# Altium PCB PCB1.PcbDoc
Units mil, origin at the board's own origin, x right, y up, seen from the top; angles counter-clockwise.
Board outline 6000 x 4000 mil, 2 copper layers (Top Layer, Bottom Layer); 53 components, 98 nets, 821 pads, 0 vias.
Unrouted connection lines stored in the file: 466.
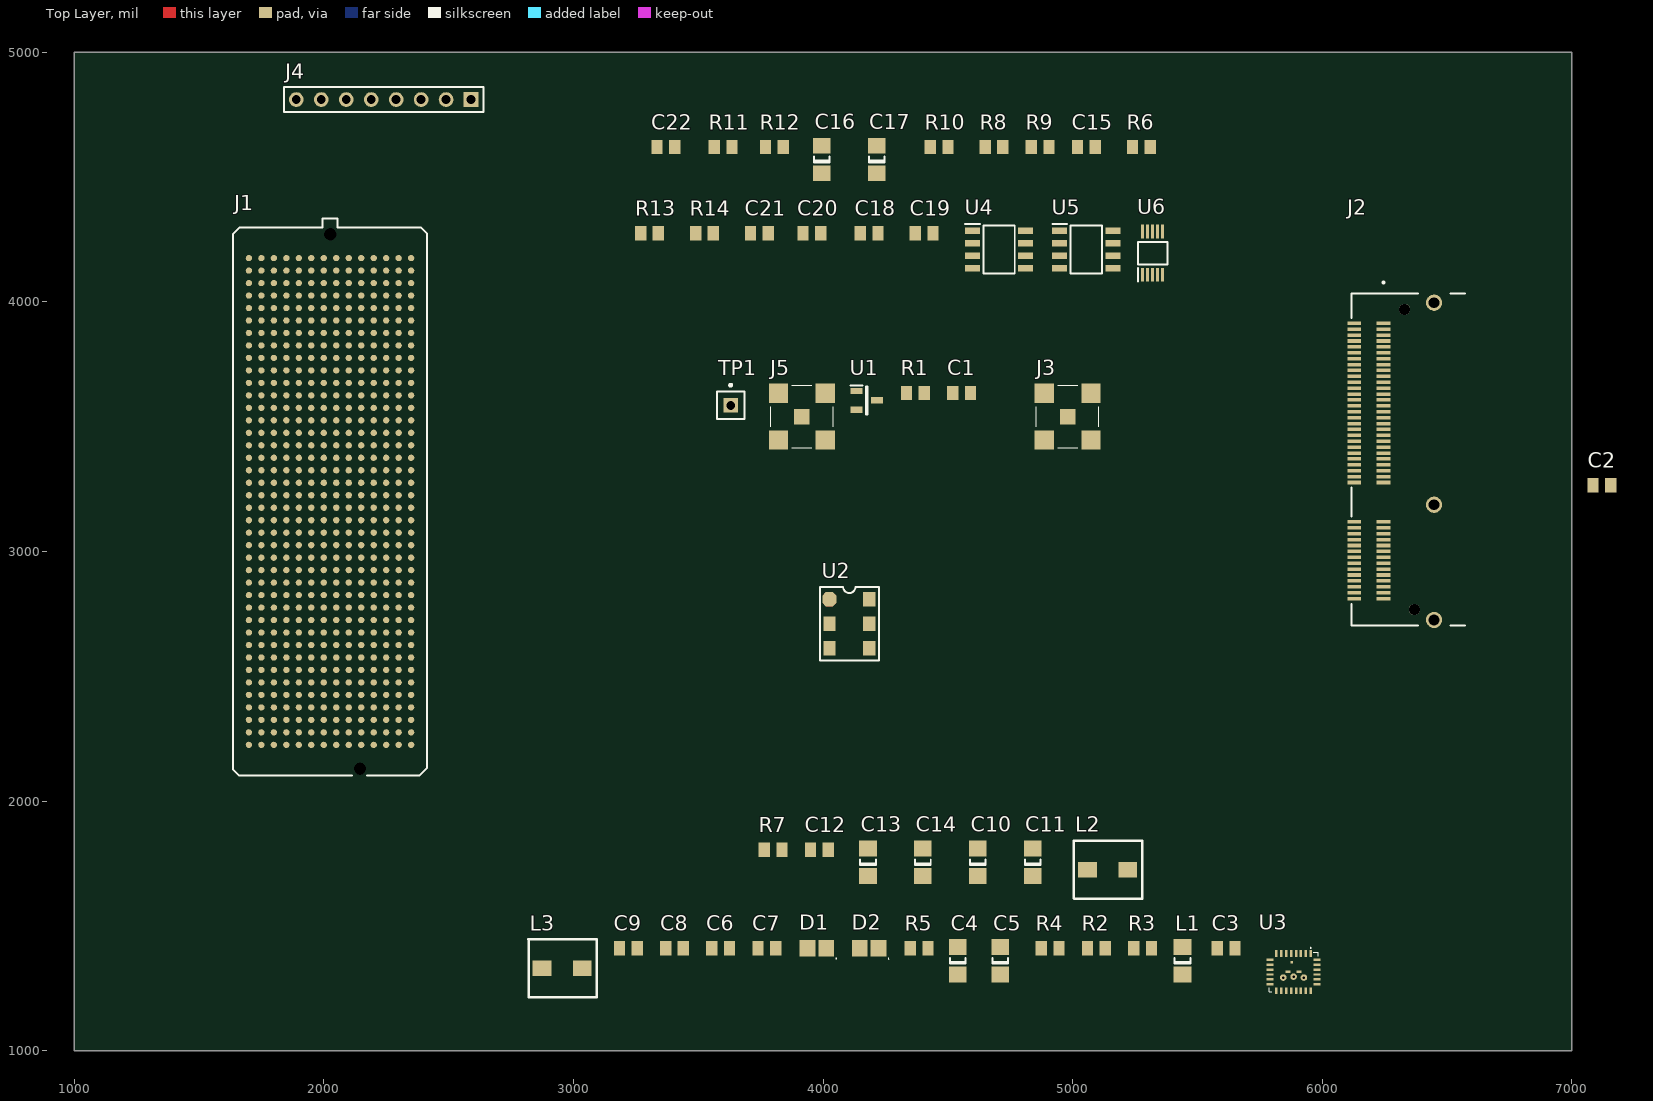
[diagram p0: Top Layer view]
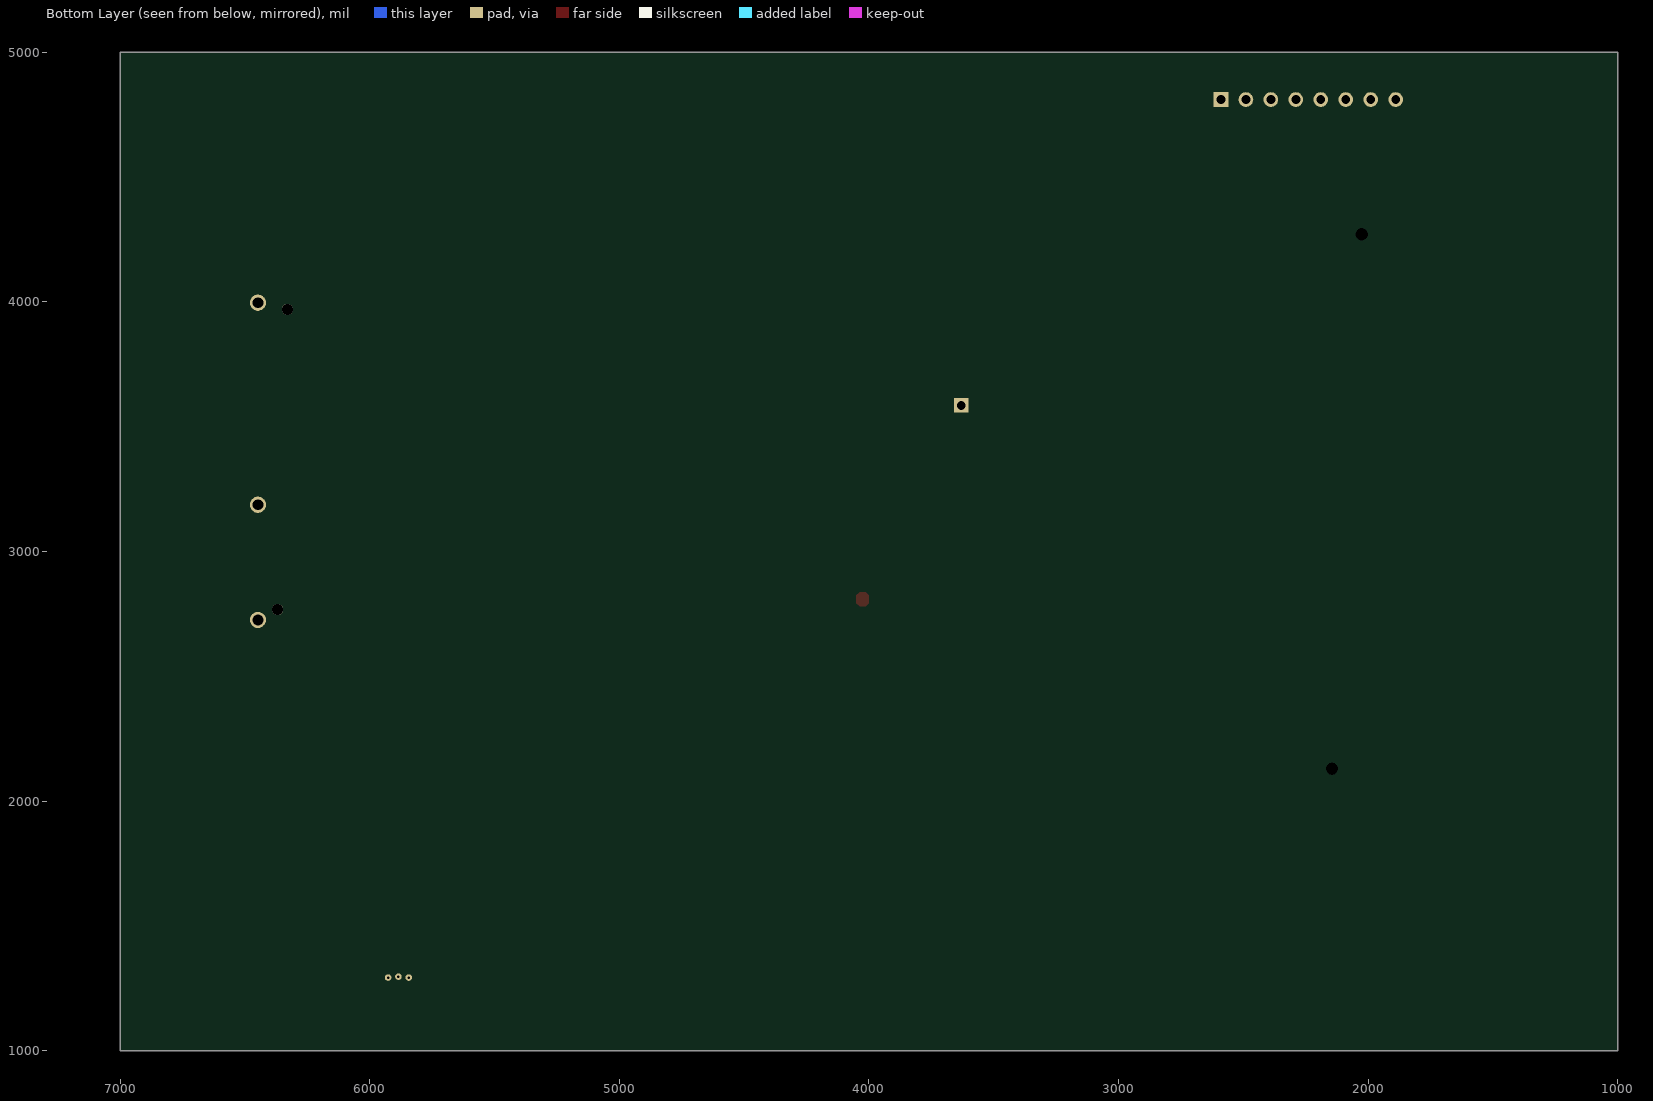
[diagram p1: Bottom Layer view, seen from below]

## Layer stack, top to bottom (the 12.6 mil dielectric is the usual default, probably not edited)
Top Solder: solder mask 0.4, Solder Resist, Dk 3.5
Top Layer: signal copper 1.4
Dielectric 1: dielectric 12.6, FR-4, Dk 4.8
Bottom Layer: signal copper 1.4
Bottom Solder: solder mask 0.4, Solder Resist, Dk 3.5

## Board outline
1000,1000 7000,1000 7000,5000 1000,5000

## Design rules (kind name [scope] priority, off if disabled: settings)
Clearance [All] p1: gap=10 ignorepadtopadclearanceinfootprint=FALSE
DiffPairsRouting [All] p1: maxlimit=10 minlimit=10 mostfreqgap=10 toplayer_minwidth=15 toplayer_maxwidth=15 toplayer_prefwidth=15 bottomlayer_minwidth=15 bottomlayer_maxwidth=15 bottomlayer_prefwidth=15 maxuncoupledlength=500
PolygonConnect [All] p1: connectstyle=Relief reliefconductorwidth=10 reliefentries=4 polygonreliefangle="90 Angle" airgapwidth=10
RoutingVias [All] p1: holewidth=28 width=50 viastyle="Through Hole" minholewidth=28 minwidth=50 maxholewidth=28 maxwidth=50
SolderMaskExpansion [All] p1: expansion=4 istentingtop=FALSE
SupplyNets "Schematic Supply Nets_4" [InNet('3V3')] p1: voltage=0.000
SupplyNets "Schematic Supply Nets_3" [InNet('2V5')] p2: voltage=0.000
SupplyNets "Schematic Supply Nets_2" [InNet('GND')] p3: voltage=0.000
SupplyNets "Schematic Supply Nets_1" [InNet('1V5')] p4: voltage=0.000
SupplyNets "Schematic Supply Nets" [InNet('VADJ_FMC')] p5: voltage=0.000
Width [All] p1: maxlimit=10 minlimit=10 preferedwidth=10
29 further rules are at their usual default settings.

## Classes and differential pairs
component class TP4_Compact_FMC_Sht2: C3 C4 C5 C6 C7 C8 C9 C10 C11 C12 C13 C14 C15 C16 C17 C18 C19 C20 C21 C22 D1 D2 J2 L1 L2 L3 R2 R3 R4 R5 R6 R7 R8 R9 R10 R11 R12 R13 R14 U3 U4 U5 U6
component class TP4_Compact_FMC_Sht1: C1 C2 J1 J3 J4 J5 R1 TP1 U1 U2
differential pair TPX4_RefClk: +TPX4_RefClk_P -TPX4_RefClk_N
differential pair TO_SYNC_B: +TO_SYNC_B_P -TO_SYNC_B_N
differential pair TESTOUT_T: +TESTOUT_T_P -TESTOUT_T_N
differential pair TESTOUT_B: +TESTOUT_B_P -TESTOUT_B_N
differential pair SHUTTER_B: +SHUTTER_B_P -SHUTTER_B_N
differential pair SERIAL_OUT5_T: +SERIAL_OUT5_T_P -SERIAL_OUT5_T_N
differential pair SERIAL_OUT5_B: +SERIAL_OUT5_B_P -SERIAL_OUT5_B_N
differential pair SERIAL_OUT4_T: +SERIAL_OUT4_T_P -SERIAL_OUT4_T_N
differential pair SERIAL_OUT4_B: +SERIAL_OUT4_B_P -SERIAL_OUT4_B_N
differential pair SERIAL_OUT3_T: +SERIAL_OUT3_T_P -SERIAL_OUT3_T_N
differential pair SERIAL_OUT3_B: +SERIAL_OUT3_B_P -SERIAL_OUT3_B_N
differential pair SERIAL_OUT2_T: +SERIAL_OUT2_T_P -SERIAL_OUT2_T_N
differential pair SERIAL_OUT2_B: +SERIAL_OUT2_B_P -SERIAL_OUT2_B_N
differential pair SERIAL_OUT1_T: +SERIAL_OUT1_T_P -SERIAL_OUT1_T_N
differential pair SERIAL_OUT1_B: +SERIAL_OUT1_B_P -SERIAL_OUT1_B_N
differential pair SERIAL_OUT0_T: +SERIAL_OUT0_T_P -SERIAL_OUT0_T_N
differential pair SERIAL_OUT0_B: +SERIAL_OUT0_B_P -SERIAL_OUT0_B_N
differential pair SC_DATA_OUT_B: +SC_DATA_OUT_B_P -SC_DATA_OUT_B_N
differential pair SC_DATA_IN_B: +SC_DATA_IN_B_P -SC_DATA_IN_B_N
differential pair SC_CLOCK_OUT_B: +SC_CLOCK_OUT_B_P -SC_CLOCK_OUT_B_N
differential pair SC_CLOCK_IN_B: +SC_CLOCK_IN_B_P -SC_CLOCK_IN_B_N
differential pair RESET_B: +RESET_B_P -RESET_B_N
differential pair MGTREF: +MGTREF_P -MGTREF_N

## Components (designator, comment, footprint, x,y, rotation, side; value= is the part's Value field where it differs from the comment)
C1 "Cap" CAP0805 4555,3635 r0 top value="10uF 16v 0805"
C2 "Cap" CAP0805 7120,3265 r0 top value="10uF 16v 0805"
C3 "Cap" CAP0805 5615,1410 r0 top value="10uF 16v 0805"
C4 "Cap" 1206 4540,1360 r90 top value="47uF 25v 1206"
C5 "Cap" 1206 4710,1360 r90 top value="47uF 25v 1206"
C6 "Cap" CAP0805 3590,1410 r0 top value=DNP
C7 "Cap" CAP0805 3775,1410 r0 top value=DNP
C8 "Cap" CAP0805 3405,1410 r0 top value="0.1uF 16v 0805"
C9 "Cap" CAP0805 3220,1410 r0 top value="0.1uF 16v 0805"
C10 "Cap" 1206 4620,1755 r90 top value="47uF 25v 1206"
C11 "Cap" 1206 4840,1755 r90 top value="47uF 25v 1206"
C12 "Cap" CAP0805 3985,1805 r0 top value="22pF 0805"
C13 "Cap" 1206 4180,1755 r90 top value="47uF 25v 1206"
C14 "Cap" 1206 4400,1755 r90 top value="47uF 25v 1206"
C15 "Cap" CAP0805 5055,4620 r0 top value="22pF 0805"
C16 "Cap" 1206 3995,4570 r90 top value="47uF 25v 1206"
C17 "Cap" 1206 4215,4570 r90 top value="47uF 25v 1206"
C18 "Cap" CAP0805 4185,4275 r0 top value="0.1uF 16v 0805"
C19 "Cap" CAP0805 4405,4275 r0 top value="0.1uF 16v 0805"
C20 "Cap" CAP0805 3955,4275 r0 top value="0.1uF 16v 0805"
C21 "Cap" CAP0805 3745,4275 r0 top value="0.1uF 16v 0805"
C22 "Cap" CAP0805 3370,4620 r0 top value="0.1uF 16v 0805"
D1 "LED_GRN 0603" LED0603 3975,1410 r0 top
D2 "LED_GRN 0603" LED0603 4185,1410 r0 top
J1 "ASP_184330_01" SAMTEC_ASP_184330_01 2025,3200 r90 top
J2 "HSEC6-042-01-S-RA-WT-X" SAMTEC_HSEC6-042-01-S-RA-WT-X 6329.65,3368.33 r90 top
J3 "SMA_V" SMA_Vert 4980,3540 r0 top
J4 "Header 8" HDR1X8 2590,4810 r180 top
J5 "SMA_V" SMA_Vert 3915,3540 r0 top
L1 "Inductor Iron" 1206 5440,1360 r90 top value="bead 1206"
L2 "Inductor Iron" Inductor_5.6mm 5140,1725 r0 top value=10mH
L3 "Inductor Iron" Inductor_5.6mm 2955,1330 r0 top value=10mH
R1 "Res" CAP0805 4370,3635 r0 top value=zero
R2 "Res1" CAP0805 5095,1410 r0 top value=15k
R3 "Res1" CAP0805 5280,1410 r0 top value=15k
R4 "Res1" CAP0805 4910,1410 r0 top value=150k
R5 "Res1" CAP0805 4385,1410 r0 top value=zero
R6 "Res1" CAP0805 5275,4620 r0 top value=45.3k
R7 "Res1" CAP0805 3800,1805 r0 top value=15k
R8 "Res1" CAP0805 4685,4620 r0 top value=10k
R9 "Res1" CAP0805 4870,4620 r0 top value=10k
R10 "Res1" CAP0805 4465,4620 r0 top value=zero
R11 "Res" CAP0805 3600,4620 r0 top value=".02 1W 1206"
R12 "Res" CAP0805 3805,4620 r0 top value=".02 1W 1206"
R13 "Res1" CAP0805 3305,4275 r0 top value=zero
R14 "Res1" CAP0805 3525,4275 r0 top value=zero
TP1 "through-hole pad" Pin1 3630,3585 r0 top
U1 "MCP1700T-2502E_TT" SOT95P237X112-3N 4175,3605 r0 top
U2 "SIT9365AI-2E2-25E160.00" osc_7mm_5mm 4025.55,2808.43 r0 top
U3 "LTC3636EUFD#PBF" LTC3636EUFDPBF 5885,1315 r0 top
U4 "AD8202WYRZ" SOIC127P600X175-8N 4705,4210 r0 top
U5 "AD8202WYRZ" SOIC127P600X175-8N 5055,4210 r0 top
U6 "ADS1015LIDGSR" SOP50P490X110-10N 5320,4195 r90 top

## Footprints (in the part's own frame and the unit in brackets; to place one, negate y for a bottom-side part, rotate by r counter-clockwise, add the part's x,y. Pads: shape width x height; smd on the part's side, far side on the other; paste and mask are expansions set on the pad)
1206 [mm] "Chip Capacitor; Body 3.2 x 1.6 mm (LxW typ)"
  rect 1.6x1.8 smd: 1(-1.4,0) 2(1.4,0)
  silkscreen extent -0.3,-0.8 0.3,0.8
CAP0805 [mm]
  rect 1.15x1.45 smd: 1(-0.9,0) 2(0.9,0)
  body extent -1.08,-0.7 1.07,0.7, height 1
HDR1X8 [mm]
  rect 1.5x1.5 hole 0.9: 1(0,0)
  round 1.5 hole 0.9: 2(2.54,0) 3(5.08,0) 4(7.62,0) 5(10.16,0) 6(12.7,0) 7(15.24,0) 8(17.78,0)
  silkscreen extent -1.27,-1.27 19.05,1.27
Inductor_5.6mm [mm]
  rect 1.9x1.6 smd: 1(-2.05,0) 2(2.05,0)
  silkscreen extent -3.43,-2.95 3.51,2.95
LED0603 [mm]
  rect 1.6x1.65 smd: 1(-0.95,0) 2(0.95,0)
  silkscreen extent 1.91,-1.09 2.01,-0.99, body extent -1.35,-0.8 1.35,0.8, height 1
LTC3636EUFDPBF [mm]
  rect 0.25x0.7 smd: 1(1.75,1.9) 2(1.25,1.9) 3(0.75,1.9) 4(0.25,1.9) 5(-0.25,1.9) 6(-0.75,1.9) 7(-1.25,1.9) 8(-1.75,1.9) 15(-1.75,-1.9) 16(-1.25,-1.9) 17(-0.75,-1.9) 18(-0.25,-1.9) 19(0.25,-1.9) 20(0.75,-1.9) 21(1.25,-1.9) 22(1.75,-1.9)
  rect 0.7x0.25 smd: 9(-2.4,1.25) 10(-2.4,0.75) 11(-2.4,0.25) 12(-2.4,-0.25) 13(-2.4,-0.75) 14(-2.4,-1.25) 23(2.4,-1.25) 24(2.4,-0.75) 25(2.4,-0.25) 26(2.4,0.25) 27(2.4,0.75) 28(2.4,1.25)
  rect 0.23x0.28 smd: 29(-0.19,1)
  rect 0.53x0.25 smd: 30(0.565,0.03) 31(-0.565,0.03)
  round 0.667 hole 0.25: 32(0,-0.47) 33(1.05,-0.56) 34(-1.05,-0.56)
  silkscreen extent -2.5,-2 2.5,2.5, body extent -2.5,-2 2.5,2, height 0.9
osc_7mm_5mm [mm]
  oct 1.45x1.45 smd: 1(0,0)
  rect 1.25x1.45 smd: 2(0,-2.5) 3(0,-5) 4(4.05,-5) 5(4.05,-2.5) 6(4.05,0)
  Top Layer region: -0.625,-0.412 -0.312,-0.725 0.312,-0.725 0.625,-0.412 0.625,0.412 0.312,0.725 -0.312,0.725 -0.625,0.412
  silkscreen extent -0.97,-6.25 5.05,1.25
Pin1 [mm]
  rect 1.5x1.5 hole 0.9: 1(0,0)
  silkscreen extent -1.4,-1.4 1.4,2.17
SAMTEC_ASP_184330_01 [mm]
  round 0.64 smd: A1(24.765,5.715) A2(23.495,5.715) A3(22.225,5.715) A4(20.955,5.715) A5(19.685,5.715) A6(18.415,5.715) A7(17.145,5.715) A8(15.875,5.715) A9(14.605,5.715) A10(13.335,5.715) A11(12.065,5.715) A12(10.795,5.715) A13(9.525,5.715) A14(8.255,5.715) A15(6.985,5.715) A16(5.715,5.715) A17(4.445,5.715) A18(3.175,5.715) A19(1.905,5.715) A20(0.635,5.715) A21(-0.635,5.715) A22(-1.905,5.715) A23(-3.175,5.715) A24(-4.445,5.715) A25(-5.715,5.715) A26(-6.985,5.715) A27(-8.255,5.715) A28(-9.525,5.715) A29(-10.795,5.715) A30(-12.065,5.715) A31(-13.335,5.715) A32(-14.605,5.715) A33(-15.875,5.715) A34(-17.145,5.715) A35(-18.415,5.715) A36(-19.685,5.715) A37(-20.955,5.715) A38(-22.225,5.715) A39(-23.495,5.715) A40(-24.765,5.715) B1(24.765,4.445) B2(23.495,4.445) B3(22.225,4.445) B4(20.955,4.445) B5(19.685,4.445) B6(18.415,4.445) B7(17.145,4.445) B8(15.875,4.445) B9(14.605,4.445) B10(13.335,4.445) B11(12.065,4.445) B12(10.795,4.445) B13(9.525,4.445) B14(8.255,4.445) B15(6.985,4.445) B16(5.715,4.445) B17(4.445,4.445) B18(3.175,4.445) B19(1.905,4.445) B20(0.635,4.445) B21(-0.635,4.445) B22(-1.905,4.445) B23(-3.175,4.445) B24(-4.445,4.445) B25(-5.715,4.445) B26(-6.985,4.445) B27(-8.255,4.445) B28(-9.525,4.445) B29(-10.795,4.445) B30(-12.065,4.445) B31(-13.335,4.445) B32(-14.605,4.445) B33(-15.875,4.445) B34(-17.145,4.445) B35(-18.415,4.445) B36(-19.685,4.445) B37(-20.955,4.445) B38(-22.225,4.445) B39(-23.495,4.445) B40(-24.765,4.445) C1(24.765,3.175) C2(23.495,3.175) C3(22.225,3.175) C4(20.955,3.175) C5(19.685,3.175) C6(18.415,3.175) C7(17.145,3.175) C8(15.875,3.175) C9(14.605,3.175) C10(13.335,3.175) C11(12.065,3.175) C12(10.795,3.175) C13(9.525,3.175) C14(8.255,3.175) C15(6.985,3.175) C16(5.715,3.175) C17(4.445,3.175) C18(3.175,3.175) C19(1.905,3.175) C20(0.635,3.175) C21(-0.635,3.175) C22(-1.905,3.175) C23(-3.175,3.175) C24(-4.445,3.175) C25(-5.715,3.175) C26(-6.985,3.175) C27(-8.255,3.175) C28(-9.525,3.175) C29(-10.795,3.175) C30(-12.065,3.175) C31(-13.335,3.175) C32(-14.605,3.175) C33(-15.875,3.175) C34(-17.145,3.175) C35(-18.415,3.175) C36(-19.685,3.175) C37(-20.955,3.175) C38(-22.225,3.175) C39(-23.495,3.175) C40(-24.765,3.175) D1(24.765,1.905) D2(23.495,1.905) D3(22.225,1.905) D4(20.955,1.905) D5(19.685,1.905) D6(18.415,1.905) D7(17.145,1.905) D8(15.875,1.905) D9(14.605,1.905) D10(13.335,1.905) D11(12.065,1.905) D12(10.795,1.905) D13(9.525,1.905) D14(8.255,1.905) D15(6.985,1.905) D16(5.715,1.905) D17(4.445,1.905) D18(3.175,1.905) D19(1.905,1.905) D20(0.635,1.905) D21(-0.635,1.905) D22(-1.905,1.905) D23(-3.175,1.905) D24(-4.445,1.905) D25(-5.715,1.905) D26(-6.985,1.905) D27(-8.255,1.905) D28(-9.525,1.905) D29(-10.795,1.905) D30(-12.065,1.905) D31(-13.335,1.905) D32(-14.605,1.905) D33(-15.875,1.905) D34(-17.145,1.905) D35(-18.415,1.905) D36(-19.685,1.905) D37(-20.955,1.905) D38(-22.225,1.905) D39(-23.495,1.905) D40(-24.765,1.905) E1(24.765,0.635) E2(23.495,0.635) E3(22.225,0.635) E4(20.955,0.635) E5(19.685,0.635) E6(18.415,0.635) E7(17.145,0.635) E8(15.875,0.635) E9(14.605,0.635) E10(13.335,0.635) E11(12.065,0.635) E12(10.795,0.635) E13(9.525,0.635) E14(8.255,0.635) E15(6.985,0.635) E16(5.715,0.635) E17(4.445,0.635) E18(3.175,0.635) E19(1.905,0.635) E20(0.635,0.635) E21(-0.635,0.635) E22(-1.905,0.635) E23(-3.175,0.635) E24(-4.445,0.635) E25(-5.715,0.635) E26(-6.985,0.635) E27(-8.255,0.635) E28(-9.525,0.635) E29(-10.795,0.635) E30(-12.065,0.635) E31(-13.335,0.635) E32(-14.605,0.635) E33(-15.875,0.635) E34(-17.145,0.635) E35(-18.415,0.635) E36(-19.685,0.635) E37(-20.955,0.635) E38(-22.225,0.635) E39(-23.495,0.635) E40(-24.765,0.635) F1(24.765,-0.635) F2(23.495,-0.635) F3(22.225,-0.635) F4(20.955,-0.635) F5(19.685,-0.635) F6(18.415,-0.635) F7(17.145,-0.635) F8(15.875,-0.635) F9(14.605,-0.635) F10(13.335,-0.635) F11(12.065,-0.635) F12(10.795,-0.635) F13(9.525,-0.635) F14(8.255,-0.635) F15(6.985,-0.635) F16(5.715,-0.635) F17(4.445,-0.635) F18(3.175,-0.635) F19(1.905,-0.635) F20(0.635,-0.635) F21(-0.635,-0.635) F22(-1.905,-0.635) F23(-3.175,-0.635) F24(-4.445,-0.635) F25(-5.715,-0.635) F26(-6.985,-0.635) F27(-8.255,-0.635) F28(-9.525,-0.635) F29(-10.795,-0.635) F30(-12.065,-0.635) F31(-13.335,-0.635) F32(-14.605,-0.635) F33(-15.875,-0.635) F34(-17.145,-0.635) F35(-18.415,-0.635) F36(-19.685,-0.635) F37(-20.955,-0.635) F38(-22.225,-0.635) F39(-23.495,-0.635) F40(-24.765,-0.635) G1(24.765,-1.905) G2(23.495,-1.905) G3(22.225,-1.905) G4(20.955,-1.905) G5(19.685,-1.905) G6(18.415,-1.905) G7(17.145,-1.905) G8(15.875,-1.905) G9(14.605,-1.905) G10(13.335,-1.905) G11(12.065,-1.905) G12(10.795,-1.905) G13(9.525,-1.905) G14(8.255,-1.905) G15(6.985,-1.905) G16(5.715,-1.905) G17(4.445,-1.905) G18(3.175,-1.905) G19(1.905,-1.905) G20(0.635,-1.905) G21(-0.635,-1.905) G22(-1.905,-1.905) G23(-3.175,-1.905) G24(-4.445,-1.905) G25(-5.715,-1.905) G26(-6.985,-1.905) G27(-8.255,-1.905) G28(-9.525,-1.905) G29(-10.795,-1.905) G30(-12.065,-1.905) G31(-13.335,-1.905) G32(-14.605,-1.905) G33(-15.875,-1.905) G34(-17.145,-1.905) G35(-18.415,-1.905) G36(-19.685,-1.905) G37(-20.955,-1.905) G38(-22.225,-1.905) G39(-23.495,-1.905) G40(-24.765,-1.905) H1(24.765,-3.175) H2(23.495,-3.175) H3(22.225,-3.175) H4(20.955,-3.175) H5(19.685,-3.175) H6(18.415,-3.175) H7(17.145,-3.175) H8(15.875,-3.175) H9(14.605,-3.175) H10(13.335,-3.175) H11(12.065,-3.175) H12(10.795,-3.175) H13(9.525,-3.175) H14(8.255,-3.175) H15(6.985,-3.175) H16(5.715,-3.175) H17(4.445,-3.175) H18(3.175,-3.175) H19(1.905,-3.175) H20(0.635,-3.175) H21(-0.635,-3.175) H22(-1.905,-3.175) H23(-3.175,-3.175) H24(-4.445,-3.175) H25(-5.715,-3.175) H26(-6.985,-3.175) H27(-8.255,-3.175) H28(-9.525,-3.175) H29(-10.795,-3.175) H30(-12.065,-3.175) H31(-13.335,-3.175) H32(-14.605,-3.175) H33(-15.875,-3.175) H34(-17.145,-3.175) H35(-18.415,-3.175) H36(-19.685,-3.175) H37(-20.955,-3.175) H38(-22.225,-3.175) H39(-23.495,-3.175) H40(-24.765,-3.175) J1(24.765,-4.445) J2(23.495,-4.445) J3(22.225,-4.445) J4(20.955,-4.445) J5(19.685,-4.445) J6(18.415,-4.445) J7(17.145,-4.445) J8(15.875,-4.445) J9(14.605,-4.445) J10(13.335,-4.445) J11(12.065,-4.445) J12(10.795,-4.445) J13(9.525,-4.445) J14(8.255,-4.445) J15(6.985,-4.445) J16(5.715,-4.445) J17(4.445,-4.445) J18(3.175,-4.445) J19(1.905,-4.445) J20(0.635,-4.445) J21(-0.635,-4.445) J22(-1.905,-4.445) J23(-3.175,-4.445) J24(-4.445,-4.445) J25(-5.715,-4.445) J26(-6.985,-4.445) J27(-8.255,-4.445) J28(-9.525,-4.445) J29(-10.795,-4.445) J30(-12.065,-4.445) J31(-13.335,-4.445) J32(-14.605,-4.445) J33(-15.875,-4.445) J34(-17.145,-4.445) J35(-18.415,-4.445) J36(-19.685,-4.445) J37(-20.955,-4.445) J38(-22.225,-4.445) J39(-23.495,-4.445) J40(-24.765,-4.445) K1(24.765,-5.715) K2(23.495,-5.715) K3(22.225,-5.715) K4(20.955,-5.715) K5(19.685,-5.715) K6(18.415,-5.715) K7(17.145,-5.715) K8(15.875,-5.715) K9(14.605,-5.715) K10(13.335,-5.715) K11(12.065,-5.715) K12(10.795,-5.715) K13(9.525,-5.715) K14(8.255,-5.715) K15(6.985,-5.715) K16(5.715,-5.715) K17(4.445,-5.715) K18(3.175,-5.715) K19(1.905,-5.715) K20(0.635,-5.715) K21(-0.635,-5.715) K22(-1.905,-5.715) K23(-3.175,-5.715) K24(-4.445,-5.715) K25(-5.715,-5.715) K26(-6.985,-5.715) K27(-8.255,-5.715) K28(-9.525,-5.715) K29(-10.795,-5.715) K30(-12.065,-5.715) K31(-13.335,-5.715) K32(-14.605,-5.715) K33(-15.875,-5.715) K34(-17.145,-5.715) K35(-18.415,-5.715) K36(-19.685,-5.715) K37(-20.955,-5.715) K38(-22.225,-5.715) K39(-23.495,-5.715) K40(-24.765,-5.715) L1(24.765,-6.985) L2(23.495,-6.985) L3(22.225,-6.985) L4(20.955,-6.985) L5(19.685,-6.985) L6(18.415,-6.985) L7(17.145,-6.985) L8(15.875,-6.985) L9(14.605,-6.985) L10(13.335,-6.985) L11(12.065,-6.985) L12(10.795,-6.985) L13(9.525,-6.985) L14(8.255,-6.985) L15(6.985,-6.985) L16(5.715,-6.985) L17(4.445,-6.985) L18(3.175,-6.985) L19(1.905,-6.985) L20(0.635,-6.985) L21(-0.635,-6.985) L22(-1.905,-6.985) L23(-3.175,-6.985) L24(-4.445,-6.985) L25(-5.715,-6.985) L26(-6.985,-6.985) L27(-8.255,-6.985) L28(-9.525,-6.985) L29(-10.795,-6.985) L30(-12.065,-6.985) L31(-13.335,-6.985) L32(-14.605,-6.985) L33(-15.875,-6.985) L34(-17.145,-6.985) L35(-18.415,-6.985) L36(-19.685,-6.985) L37(-20.955,-6.985) L38(-22.225,-6.985) L39(-23.495,-6.985) l40(-24.765,-6.985) M1(24.765,-8.255) M2(23.495,-8.255) M3(22.225,-8.255) M4(20.955,-8.255) M5(19.685,-8.255) M6(18.415,-8.255) M7(17.145,-8.255) M8(15.875,-8.255) M9(14.605,-8.255) M10(13.335,-8.255) M11(12.065,-8.255) M12(10.795,-8.255) M13(9.525,-8.255) M14(8.255,-8.255) M15(6.985,-8.255) M16(5.715,-8.255) M17(4.445,-8.255) M18(3.175,-8.255) M19(1.905,-8.255) M20(0.635,-8.255) M21(-0.635,-8.255) M22(-1.905,-8.255) M23(-3.175,-8.255) M24(-4.445,-8.255) M25(-5.715,-8.255) M26(-6.985,-8.255) M27(-8.255,-8.255) M28(-9.525,-8.255) M29(-10.795,-8.255) M30(-12.065,-8.255) M31(-13.335,-8.255) M32(-14.605,-8.255) M33(-15.875,-8.255) M34(-17.145,-8.255) M35(-18.415,-8.255) M36(-19.685,-8.255) M37(-20.955,-8.255) M38(-22.225,-8.255) M39(-23.495,-8.255) M40(-24.765,-8.255) Y1(24.765,8.255) Y2(23.495,8.255) Y3(22.225,8.255) Y4(20.955,8.255) Y5(19.685,8.255) Y6(18.415,8.255) Y7(17.145,8.255) Y8(15.875,8.255) Y9(14.605,8.255) Y10(13.335,8.255) Y11(12.065,8.255) Y12(10.795,8.255) Y13(9.525,8.255) Y14(8.255,8.255) Y15(6.985,8.255) Y16(5.715,8.255) Y17(4.445,8.255) Y18(3.175,8.255) Y19(1.905,8.255) Y20(0.635,8.255) Y21(-0.635,8.255) Y22(-1.905,8.255) Y23(-3.175,8.255) Y24(-4.445,8.255) Y25(-5.715,8.255) Y26(-6.985,8.255) Y27(-8.255,8.255) Y28(-9.525,8.255) Y29(-10.795,8.255) Y30(-12.065,8.255) Y31(-13.335,8.255) Y32(-14.605,8.255) Y33(-15.875,8.255) Y34(-17.145,8.255) Y35(-18.415,8.255) Y36(-19.685,8.255) Y37(-20.955,8.255) Y38(-22.225,8.255) Y39(-23.495,8.255) Y40(-24.765,8.255) Z1(24.765,6.985) Z2(23.495,6.985) Z3(22.225,6.985) Z4(20.955,6.985) Z5(19.685,6.985) Z6(18.415,6.985) Z7(17.145,6.985) Z8(15.875,6.985) Z9(14.605,6.985) Z10(13.335,6.985) Z11(12.065,6.985) Z12(10.795,6.985) Z13(9.525,6.985) Z14(8.255,6.985) Z15(6.985,6.985) Z16(5.715,6.985) Z17(4.445,6.985) Z18(3.175,6.985) Z19(1.905,6.985) Z20(0.635,6.985) Z21(-0.635,6.985) Z22(-1.905,6.985) Z23(-3.175,6.985) Z24(-4.445,6.985) Z25(-5.715,6.985) Z26(-6.985,6.985) Z27(-8.255,6.985) Z28(-9.525,6.985) Z29(-10.795,6.985) Z30(-12.065,6.985) Z31(-13.335,6.985) Z32(-14.605,6.985) Z33(-15.875,6.985) Z34(-17.145,6.985) Z35(-18.415,6.985) Z36(-19.685,6.985) Z37(-20.955,6.985) Z38(-22.225,6.985) Z39(-23.495,6.985) Z40(-24.765,6.985)
  round 0.97 hole 1.27 unplated: MH1(-27.19,-3.05) MH2(27.19,0)
  silkscreen extent -27.89,-9.88 28.78,9.88, body extent -27.94,-9.91 28.83,9.91, height 6.1
SAMTEC_HSEC6-042-01-S-RA-WT-X [mm]
  rect 0.36x1.4 smd: A1(13.855,2.15) A2(13.254,2.15) A3(12.655,2.15) A4(12.054,2.15) A5(11.455,2.15) A6(10.854,2.15) A7(10.255,2.15) A8(9.654,2.15) A9(9.055,2.15) A10(8.454,2.15) A11(7.855,2.15) A12(7.254,2.15) A13(6.655,2.15) A14(6.054,2.15) A15(5.455,2.15) A16(4.854,2.15) A17(4.255,2.15) A18(3.655,2.15) A19(3.054,2.15) A20(2.455,2.15) A21(1.854,2.15) A22(1.255,2.15) A23(0.654,2.15) A24(0.055,2.15) A25(-0.546,2.15) A26(-1.145,2.15) A27(-1.746,2.15) A28(-2.345,2.15) A29(-6.355,2.15) A30(-6.956,2.15) A31(-7.555,2.15) A32(-8.156,2.15) A33(-8.755,2.15) A34(-9.356,2.15) A35(-9.955,2.15) A36(-10.556,2.15) A37(-11.155,2.15) A38(-11.756,2.15) A39(-12.355,2.15) A40(-12.956,2.15) A41(-13.555,2.15) A42(-14.155,2.15) B1(13.855,5.11) B2(13.254,5.11) B3(12.655,5.11) B4(12.054,5.11) B5(11.455,5.11) B6(10.854,5.11) B7(10.255,5.11) B8(9.654,5.11) B9(9.055,5.11) B10(8.454,5.11) B11(7.855,5.11) B12(7.254,5.11) B13(6.655,5.11) B14(6.054,5.11) B15(5.455,5.11) B16(4.854,5.11) B17(4.255,5.11) B18(3.655,5.11) B19(3.054,5.11) B20(2.455,5.11) B21(1.854,5.11) B22(1.255,5.11) B23(0.654,5.11) B24(0.055,5.11) B25(-0.546,5.11) B26(-1.145,5.11) B27(-1.746,5.11) B28(-2.345,5.11) B29(-6.355,5.11) B30(-6.956,5.11) B31(-7.555,5.11) B32(-8.156,5.11) B33(-8.755,5.11) B34(-9.356,5.11) B35(-9.955,5.11) B36(-10.556,5.11) B37(-11.155,5.11) B38(-11.756,5.11) B39(-12.355,5.11) B40(-12.956,5.11) B41(-13.555,5.11) B42(-14.155,5.11)
  round 1.65 hole 1.1: SH1(-16.328,-3) SH2(-4.607,-3) SH3(15.947,-3)
  round 1.1 hole 1.1 unplated: ""(-15.272,-1) ""(15.272,0)
  silkscreen extent -16.89,-6.15 18.1,5.4
SMA_Vert [mil] "SMA, Jack, SMT, Vertical"
  rect 62x62 smd: 1(0,0)
  rect 77x77 smd: 2(-93.5,-93.5) 2(93.5,93.5) 3(-93.5,93.5) 3(93.5,-93.5)
  silkscreen extent -125,-125 125,125, body extent -125,-125 125,125, height 375
SOIC127P600X175-8N [mm]
  rect 1.525x0.65 smd: 1(-2.712,1.905) 2(-2.712,0.635) 3(-2.712,-0.635) 4(-2.712,-1.905) 5(2.712,-1.905) 6(2.712,-0.635) 7(2.712,0.635) 8(2.712,1.905)
  silkscreen extent -3.47,-2.45 1.6,2.58, body extent -3,-2.45 3,2.45, height 1.75
SOP50P490X110-10N [mm]
  rect 1.4x0.3 smd: 1(-2.2,1) 2(-2.2,0.5) 3(-2.2,0) 4(-2.2,-0.5) 5(-2.2,-1) 6(2.2,-1) 7(2.2,-0.5) 8(2.2,0) 9(2.2,0.5) 10(2.2,1)
  silkscreen extent -2.9,-1.5 1.15,1.5, body extent -2.46,-1.5 2.46,1.5, height 1.1
SOT95P237X112-3N [mm]
  rect 1.25x0.65 smd: 1(-1.05,0.95) 2(-1.05,-0.95) 3(1.05,0)
  silkscreen extent -1.68,-1.43 0.08,1.53, body extent -1.18,-1.43 1.18,1.43, height 1.12

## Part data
C1 C2: "Capacitor, ceramic SM"
C3 C4 C5 C6 C7 C8 C9 C10 C11 C12 C13 C14 C15 C16 C17 C18 C19 C20 C21 C22: "Capacitor"
D1 D2: library part LED2, "Red LED, SM"
J1: library part FMCplus
J2: "84 Position Female Connector PCI Expressâ„¢ Gold 0.024 (0.60mm) Black", package=None
J3 J5: library part COAX-F, "Vertical mount SMA", PackageDocument=04-Jul-1999
J4: "Header, 8-Pin"
L1 L2 L3: "Magnetic-Core Inductor"
R1: library part Res3, "Resistor"
R2 R3 R4 R5 R6 R7 R8 R9 R10 R13 R14: "Resistor"
R11 R12: "Resistor, SM"
TP1: library part testpoint
U1: "Integrated Circuit", Arrow Part Number=MCP1700T-2502E/TT, Manufacturer_Name=Microchip, Mouser Part Number=579-MCP1700T2502E/TT
U2: library part CCLD-033-50-100.000
U3: "Integrated Circuit", Manufacturer_Name="Analog Devices", Mouser Part Number=584-LTC3636EUFDPBF
U4 U5: "Integrated Circuit", Manufacturer_Name="Analog Devices", Mouser Part Number=584-AD8202WYRZ
U6: "Integrated Circuit", Manufacturer_Name="Texas Instruments", Mouser Part Number=595-ADS1015LIDGSR

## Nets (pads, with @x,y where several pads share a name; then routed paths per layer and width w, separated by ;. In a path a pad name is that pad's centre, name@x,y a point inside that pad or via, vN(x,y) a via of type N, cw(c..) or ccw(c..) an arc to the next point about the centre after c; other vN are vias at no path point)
1V5: C12.2 C13.2 C14.2 L3.2 R7.2 R11.2 R12.2 U4.8 U5.8
1V5AN: C16.2 J2.B38 J2.B41 R11.1 U4.1
1V5DIG: C17.2 J2.A38 J2.A41 R12.1 U5.1
2V5: C2.1 C22.2 U1.2 U2.6 U6.8
3V3: C1.1 C10.2 C11.2 C15.2 C18.2 C19.2 J2.A29 L2.1 R6.2 U1.3 U4.6 U5.6
12V0RAW: J1.C35 J1.C37 J1.L36 J1.L37 J1.l40 L1.2 R2.2 R3.2
DIGITALPIXEL0_B: J1.D26 J2.B39
DIGITALPIXEL0_T: J1.D23 J2.B36
DIGITALPIXEL1_B: J1.D27 J2.B40
DIGITALPIXEL1_T: J1.D24 J2.B37
GND: C1.2 C2.2 C3.1 C4.1 C5.1 C6.2 C7.1 C10.1 C11.1 C13.1 C14.1 C16.1 C17.1 C18.1 C19.1 C20.1 C21.1 C22.1 D1.2 D2.2 J1.A1 J1.A4 J1.A5 J1.A8 J1.A9 J1.A12 J1.A13 J1.A16 J1.A17 J1.A20 J1.A21 J1.A24 J1.A25 J1.A28 J1.A29 J1.A32 J1.A33 J1.A36 J1.A37 J1.A40 J1.B2 J1.B3 J1.B6 J1.B7 J1.B10 J1.B11 J1.B14 J1.B15 J1.B18 J1.B19 J1.B22 J1.B23 J1.B26 J1.B27 J1.B30 J1.B31 J1.B34 J1.B35 J1.B38 J1.B39 J1.C1 J1.C4 J1.C5 J1.C8 J1.C9 J1.C12 J1.C13 J1.C16 J1.C17 J1.C20 J1.C21 J1.C24 J1.C25 J1.C28 J1.C29 J1.C32 J1.C33 J1.C36 J1.C38 J1.C40 J1.D2 J1.D3 J1.D6 J1.D7 J1.D10 J1.D13 J1.D16 J1.D19 J1.D22 J1.D25 J1.D28 J1.D37 J1.D39 J1.E1 J1.E4 J1.E5 J1.E8 J1.E11 J1.E14 J1.E17 J1.E20 J1.E23 J1.E26 J1.E29 J1.E32 J1.E35 J1.E38 J1.E40 J1.F2 J1.F3 J1.F6 J1.F9 J1.F12 J1.F15 J1.F18 J1.F21 J1.F24 J1.F27 J1.F30 J1.F33 J1.F36 J1.F39 J1.G1 J1.G4 J1.G5 J1.G8 J1.G11 J1.G14 J1.G17 J1.G20 J1.G23 J1.G26 J1.G29 J1.G32 J1.G35 J1.G38 J1.G40 J1.H3 J1.H6 J1.H9 J1.H12 J1.H15 J1.H18 J1.H21 J1.H24 J1.H27 J1.H30 J1.H33 J1.H36 J1.H39 J1.J1 J1.J4 J1.J5 J1.J8 J1.J11 J1.J14 J1.J17 J1.J20 J1.J23 J1.J26 J1.J29 J1.J32 J1.J35 J1.J38 J1.J40 J1.K2 J1.K3 J1.K6 J1.K9 J1.K12 J1.K15 J1.K18 J1.K21 J1.K24 J1.K27 J1.K30 J1.K33 J1.K36 J1.K39 J1.L2 J1.L3 J1.L6 J1.L7 J1.L10 J1.L11 J1.L14 J1.L15 J1.L18 J1.L19 J1.L22 J1.L23 J1.L26 J1.L27 J1.L30 J1.L31 J1.L34 J1.L35 J1.L38 J1.L39 J1.M1 J1.M4 J1.M5 J1.M8 J1.M9 J1.M12 J1.M13 J1.M16 J1.M17 J1.M20 J1.M21 J1.M24 J1.M25 J1.M28 J1.M29 J1.M32 J1.M33 J1.M36 J1.M37 J1.M40 J1.Y1 J1.Y4 J1.Y5 J1.Y8 J1.Y9 J1.Y12 J1.Y13 J1.Y16 J1.Y17 J1.Y20 J1.Y21 J1.Y24 J1.Y25 J1.Y28 J1.Y29 J1.Y32 J1.Y33 J1.Y36 J1.Y37 J1.Y40 J1.Z2 J1.Z3 J1.Z6 J1.Z7 J1.Z10 J1.Z11 J1.Z14 J1.Z15 J1.Z18 J1.Z19 J1.Z22 J1.Z23 J1.Z26 J1.Z27 J1.Z30 J1.Z31 J1.Z34 J1.Z35 J1.Z38 J1.Z39 J2.A1 J2.A4 J2.A7 J2.A10 J2.A13 J2.A16 J2.A19 J2.A22 J2.A25 J2.A28 J2.A32 J2.B1 J2.B4 J2.B7 J2.B10 J2.B13 J2.B16 J2.B19 J2.B22 J2.B25 J2.B28 J2.B29 J2.B32 J2.B35 J3.2 J3.3 J5.2 J5.3 R1.1 R4.1 R5.1 R8.1 R10.1 R13.1 R14.1 TP1.1 U1.1 U2.1 U2.3 U3.12 U3.18 U3.19 U3.25 U3.30 U3.31 U3.32 U4.2 U5.2 U6.1 U6.3
I2C_SCL: J1.C30 J2.A42 U6.10
I2C_SDA: J1.C31 J2.B42 U6.9
IMON1V5AN: U4.5 U6.5
IMON1V5DIG: U5.5 U6.4
INTVCC: C3.2 U3.1 U3.5 U3.8 U3.29
MGTREF_N: J1.B21 U2.5
MGTREF_P: J1.B20 U2.4
NetC4_2: C4.2 C5.2 L1.1 U3.15 U3.16 U3.21 U3.22
NetC6_1: C6.1 U3.11
NetC7_2: C7.2 U3.26
NetC8_1: C8.1 L3.1 U3.20 U3.24 U3.33
NetC8_2: C8.2 U3.23
NetC9_1: C9.1 L2.2 U3.13 U3.17 U3.34
NetC9_2: C9.2 U3.14
NetC12_1: C12.1 R7.1 R9.2 U3.28
NetC15_1: C15.1 R6.1 R8.2 U3.9
NetC20_2: C20.2 U4.3 U4.4
NetC21_2: C21.2 U5.3 U5.4
NetJ1_d30: J1.D30 J1.D31
NetJ1_h2: J1.H2 R1.2
NetR4_2: R4.2 U3.4
NetR5_2: R5.2 U3.3
NetR9_1: R9.1 R10.2
NetR13_2: R13.2 U6.6
NetR14_2: R14.2 U6.7
PGOOD1: D1.1 R2.1 U3.27
PGOOD2: D2.1 R3.1 U3.10
PWR_EN: U3.2 U3.7
RESET_B_N: J1.D12 J2.A37
RESET_B_P: J1.D11 J2.A36
SC_CLOCK_IN_B_N: J1.C27 J2.A31
SC_CLOCK_IN_B_P: J1.C26 J2.A30
SC_CLOCK_OUT_B_N: J1.D18 J2.B31
SC_CLOCK_OUT_B_P: J1.D17 J2.B30
SC_DATA_IN_B_N: J1.D21 J2.B34
SC_DATA_IN_B_P: J1.D20 J2.B33
SC_DATA_OUT_B_N: J1.D9 J2.A34
SC_DATA_OUT_B_P: J1.D8 J2.A33
SERIAL_OUT0_B_N: J1.B17 J2.A15
SERIAL_OUT0_B_P: J1.B16 J2.A14
SERIAL_OUT0_T_N: J1.C7 J2.A3
SERIAL_OUT0_T_P: J1.C6 J2.A2
SERIAL_OUT1_B_N: J1.B13 J2.B12
SERIAL_OUT1_B_P: J1.B12 J2.B11
SERIAL_OUT1_T_N: J1.A3 J2.A6
SERIAL_OUT1_T_P: J1.A2 J2.A5
SERIAL_OUT2_B_N: J1.B9 J2.A18
SERIAL_OUT2_B_P: J1.B8 J2.A17
SERIAL_OUT2_T_N: J1.A7 J2.B3
SERIAL_OUT2_T_P: J1.A6 J2.B2
SERIAL_OUT3_B_N: J1.B5 J2.A12
SERIAL_OUT3_B_P: J1.B4 J2.A11
SERIAL_OUT3_T_N: J1.A11 J2.A9
SERIAL_OUT3_T_P: J1.A10 J2.A8
SERIAL_OUT4_B_N: J1.Y11 J2.B9
SERIAL_OUT4_B_P: J1.Y10 J2.B8
SERIAL_OUT4_T_N: J1.A15 J2.B6
SERIAL_OUT4_T_P: J1.A14 J2.B5
SERIAL_OUT5_B_N: J1.Z13 J2.B18
SERIAL_OUT5_B_P: J1.Z12 J2.B17
SERIAL_OUT5_T_N: J1.A19 J2.B15
SERIAL_OUT5_T_P: J1.A18 J2.B14
SHUTTER_B_N: J1.C23 J2.B21
SHUTTER_B_P: J1.C22 J2.B20
SPARE0: J1.G9 J2.B23
SPARE1: J1.G10 J2.B24
SPARE2: J1.G12 J2.B26
SPARE3: J1.G13 J2.B27
TESTOUT_B_N: J1.C15 J2.A24
TESTOUT_B_P: J1.C14 J2.A23
TESTOUT_T_N: J1.C19 J2.A27
TESTOUT_T_P: J1.C18 J2.A26
TO_SYNC_B_N: J1.D15 J2.A40
TO_SYNC_B_P: J1.D14 J2.A39
TP0: J1.G15 J4.1
TP1: J1.G16 J4.2
TP2: J1.G18 J4.3
TP3: J1.G19 J4.4
TP4: J1.G21 J4.5
TP5: J1.G22 J4.6
TP6: J1.G24 J4.7
TP7: J1.G25 J4.8
TP8: J1.G27 J3.1
TP9: J1.G28 J5.1
TPX4_RefClk_N: J1.C11 J2.A21
TPX4_RefClk_P: J1.C10 J2.A20
VADJ_FMC: J1.E39 J1.F40 J1.H40
pads on no net: J1.A22 J1.A23 J1.A26 J1.A27 J1.A30 J1.A31 J1.A34 J1.A35 J1.A38 J1.A39 J1.B1 J1.B24 J1.B25 J1.B28 J1.B29 J1.B32 J1.B33 J1.B36 J1.B37 J1.B40 J1.C2 J1.C3 J1.C34 J1.C39 J1.D1 J1.D4 J1.D5 J1.D29 J1.D32 J1.D33 J1.D34 J1.D35 J1.D36 J1.D38 J1.D40 J1.E2 J1.E3 J1.E6 J1.E7 J1.E9 J1.E10 J1.E12 J1.E13 J1.E15 J1.E16 J1.E18 J1.E19 J1.E21 J1.E22 J1.E24 J1.E25 J1.E27 J1.E28 J1.E30 J1.E31 J1.E33 J1.E34 J1.E36 J1.E37 J1.F1 J1.F4 J1.F5 J1.F7 J1.F8 J1.F10 J1.F11 J1.F13 J1.F14 J1.F16 J1.F17 J1.F19 J1.F20 J1.F22 J1.F23 J1.F25 J1.F26 J1.F28 J1.F29 J1.F31 J1.F32 J1.F34 J1.F35 J1.F37 J1.F38 J1.G2 J1.G3 J1.G6 J1.G7 J1.G30 J1.G31 J1.G33 J1.G34 J1.G36 J1.G37 J1.G39 J1.H1 J1.H4 J1.H5 J1.H7 J1.H8 J1.H10 J1.H11 J1.H13 J1.H14 J1.H16 J1.H17 J1.H19 J1.H20 J1.H22 J1.H23 J1.H25 J1.H26 J1.H28 J1.H29 J1.H31 J1.H32 J1.H34 J1.H35 J1.H37 J1.H38 J1.J2 J1.J3 J1.J6 J1.J7 J1.J9 J1.J10 J1.J12 J1.J13 J1.J15 J1.J16 J1.J18 J1.J19 J1.J21 J1.J22 J1.J24 J1.J25 J1.J27 J1.J28 J1.J30 J1.J31 J1.J33 J1.J34 J1.J36 J1.J37 J1.J39 J1.K1 J1.K4 J1.K5 J1.K7 J1.K8 J1.K10 J1.K11 J1.K13 J1.K14 J1.K16 J1.K17 J1.K19 J1.K20 J1.K22 J1.K23 J1.K25 J1.K26 J1.K28 J1.K29 J1.K31 J1.K32 J1.K34 J1.K35 J1.K37 J1.K38 J1.K40 J1.L1 J1.L4 J1.L5 J1.L8 J1.L9 J1.L12 J1.L13 J1.L16 J1.L17 J1.L20 J1.L21 J1.L24 J1.L25 J1.L28 J1.L29 J1.L32 J1.L33 J1.M2 J1.M3 J1.M6 J1.M7 J1.M10 J1.M11 J1.M14 J1.M15 J1.M18 J1.M19 J1.M22 J1.M23 J1.M26 J1.M27 J1.M30 J1.M31 J1.M34 J1.M35 J1.M38 J1.M39 J1.MH1 J1.MH2 J1.Y2 J1.Y3 J1.Y6 J1.Y7 J1.Y14 J1.Y15 J1.Y18 J1.Y19 J1.Y22 J1.Y23 J1.Y26 J1.Y27 J1.Y30 J1.Y31 J1.Y34 J1.Y35 J1.Y38 J1.Y39 J1.Z1 J1.Z4 J1.Z5 J1.Z8 J1.Z9 J1.Z16 J1.Z17 J1.Z20 J1.Z21 J1.Z24 J1.Z25 J1.Z28 J1.Z29 J1.Z32 J1.Z33 J1.Z36 J1.Z37 J1.Z40 J2. J2.A35 J2.SH1 J2.SH2 J2.SH3 U2.2 U3.6 U4.7 U5.7 U6.2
